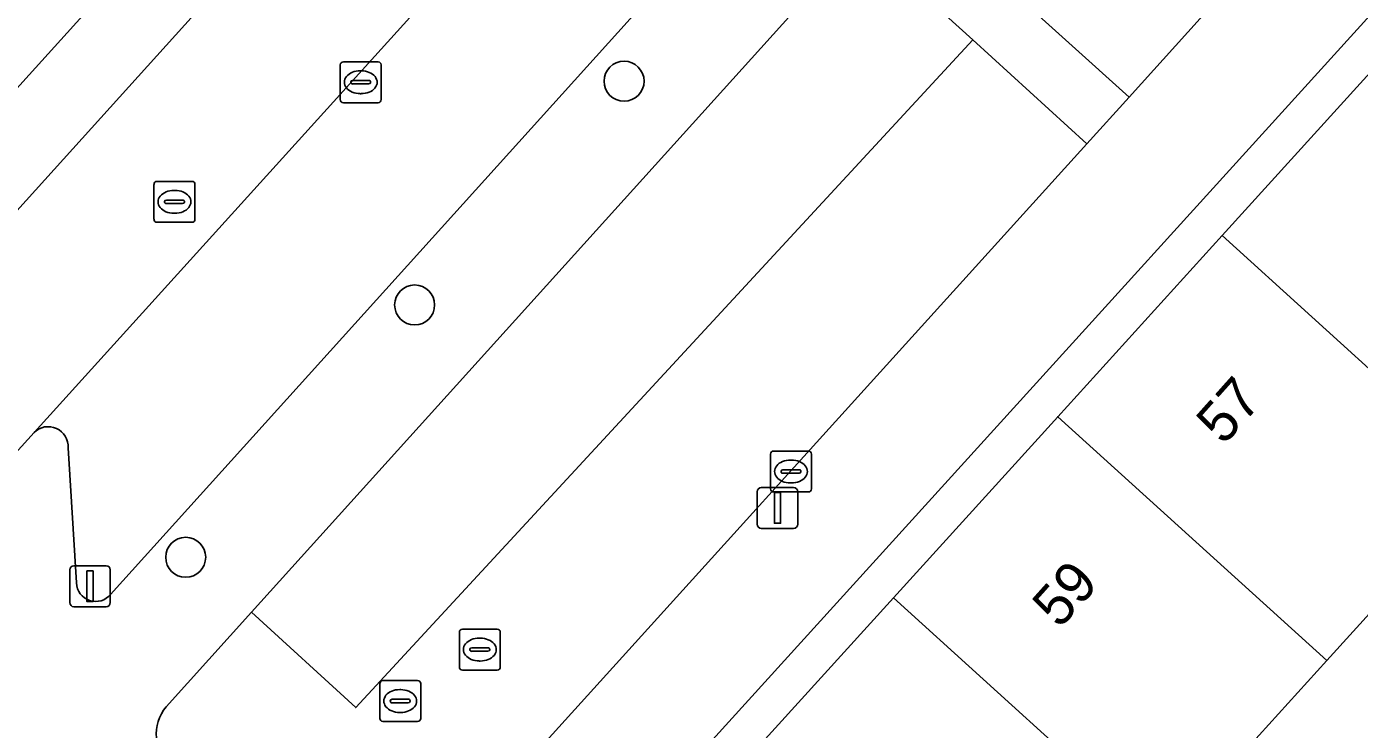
# Model space of a CAD drawing. Extents: x 159039 to 160102, y 381214 to 382524.
# Drawn here: x 159510.93 to 159543.52, y 381770.5 to 381787.69 of the extents above; entities that cross this region are included whole.
import ezdxf

# ---------------------------------------------------------------- set-up
doc = ezdxf.new("R2010")
doc.units = 0
for name, color, linetype in [('IMGEO_Boom', 7, 'Continuous'), ('IMGEO_Erf', 7, 'Continuous'), ('IMGEO_Groenvoorziening', 7, 'Continuous'), ('IMGEO_Kolk', 7, 'Continuous'), ('IMGEO_Lichtmast', 7, 'Continuous'), ('IMGEO_Pand', 7, 'Continuous'), ('IMGEO_Pand_nummerreeks', 7, 'Continuous'), ('IMGEO_Parkeervlak_open', 7, 'Continuous'), ('IMGEO_Rijbaan_lokaal_open', 7, 'Continuous'), ('IMGEO_Rioolput', 7, 'Continuous'), ('IMGEO_Voetpad_open', 7, 'Continuous')]:
    doc.layers.add(name, color=color, linetype=linetype)

msp = doc.modelspace()

# ---------------------------------------------------------------- linework, layer by layer
at = {"layer": 'IMGEO_Boom'}
for centre in [(159525.537, 381786.356), (159520.415, 381780.883), (159514.815, 381774.711)]:
    msp.add_circle(centre, 0.489, dxfattribs=at)
at = {"layer": 'IMGEO_Erf'}
for points in [[(159556.91, 381802.444), (159519.855, 381761.602)], [(159528.109, 381769.292), (159532.127, 381773.721), (159536.145, 381778.149), (159540.164, 381782.579), (159544.182, 381787.008)], [(159546.74, 381776.612), (159542.721, 381772.183), (159538.703, 381767.754), (159534.685, 381763.325), (159530.667, 381758.897), (159526.533, 381754.341), (159527.681, 381753.271), (159531.761, 381750.028), (159535.569, 381754.45), (159537.378, 381756.551)]]:
    msp.add_lwpolyline(points, dxfattribs=at)
at = {"layer": 'IMGEO_Groenvoorziening'}
for points in [[(159534.941, 381788.628), (159537.894, 381785.968), (159552.314, 381801.953)], [(159534.063, 381787.364), (159518.976, 381771.034), (159516.427, 381773.369)], [(159521.06, 381767.378), (159536.857, 381784.828), (159534.063, 381787.364)], [(159516.427, 381773.369), (159514.337, 381771.053)]]:
    msp.add_lwpolyline(points, dxfattribs=at)
msp.add_lwpolyline([(159516.427, 381773.369), (159518.976, 381771.034), (159534.063, 381787.364), (159531.315, 381789.859)], close=True, dxfattribs=at)
msp.add_arc((159515.166, 381770.375), 1.071, 140.7315, 227.7441, dxfattribs=at)
at = {"layer": 'IMGEO_Kolk'}
for p, q in [((159518.596, 381785.905), (159518.596, 381786.757)), ((159518.671, 381786.831), (159519.523, 381786.831)), ((159519.597, 381786.757), (159519.597, 381785.905)), ((159518.898, 381786.374), (159519.296, 381786.374)), ((159519.084, 381786.611), (159519.109, 381786.611)), ((159518.855, 381786.325), (159518.855, 381786.337)), ((159519.293, 381786.288), (159518.895, 381786.288)), ((159519.107, 381786.051), (159519.082, 381786.051)), ((159519.339, 381786.337), (159519.339, 381786.325)), ((159519.523, 381785.831), (159518.671, 381785.831)), ((159529.119, 381776.384), (159529.119, 381777.236)), ((159529.194, 381777.31), (159530.046, 381777.31)), ((159530.12, 381777.236), (159530.12, 381776.384)), ((159529.607, 381777.09), (159529.632, 381777.09)), ((159529.378, 381776.804), (159529.378, 381776.816)), ((159529.816, 381776.767), (159529.418, 381776.767)), ((159529.421, 381776.853), (159529.819, 381776.853)), ((159529.862, 381776.816), (159529.862, 381776.804)), ((159530.046, 381776.31), (159529.194, 381776.31)), ((159529.63, 381776.53), (159529.605, 381776.53))]:
    msp.add_line(p, q, dxfattribs=at)
for points in [[(159518.596, 381785.905), (159518.596, 381786.757)], [(159518.671, 381786.831), (159519.523, 381786.831)], [(159519.597, 381786.757), (159519.597, 381785.905)], [(159519.523, 381785.831), (159518.671, 381785.831)], [(159529.119, 381776.384), (159529.119, 381777.236)], [(159529.194, 381777.31), (159530.046, 381777.31)], [(159530.12, 381777.236), (159530.12, 381776.384)], [(159530.046, 381776.31), (159529.194, 381776.31)]]:
    msp.add_lwpolyline(points, dxfattribs=at)
for centre, radius, start, end in [((159518.673, 381786.755), 0.0765, 91.552, 178.448), ((159518.673, 381786.755), 0.0765, 91.552, 178.448), ((159519.521, 381786.755), 0.0765, 1.552, 88.448), ((159519.521, 381786.755), 0.0765, 1.552, 88.448), ((159518.895, 381786.334), 0.0403, 85.8775, 175.7526), ((159519.3, 381786.336), 0.0386, 1.7309, 96.639), ((159518.892, 381786.324), 0.0366, 178.938, 274.7102), ((159519.296, 381786.331), 0.043, 264.8664, 352.4533), ((159518.673, 381785.907), 0.0765, 181.552, 268.448), ((159518.673, 381785.907), 0.0765, 181.552, 268.448), ((159519.521, 381785.907), 0.0765, 271.552, 358.448), ((159519.521, 381785.907), 0.0765, 271.552, 358.448), ((159529.196, 381777.234), 0.0765, 91.552, 178.448), ((159529.196, 381777.234), 0.0765, 91.552, 178.448), ((159530.044, 381777.234), 0.0765, 1.552, 88.448), ((159530.044, 381777.234), 0.0765, 1.552, 88.448), ((159529.418, 381776.813), 0.0403, 85.8775, 175.7526), ((159529.415, 381776.803), 0.0366, 178.938, 274.7102), ((159529.819, 381776.81), 0.043, 264.8664, 352.4533), ((159529.823, 381776.815), 0.0386, 1.7309, 96.639), ((159529.196, 381776.386), 0.0765, 181.552, 268.448), ((159529.196, 381776.386), 0.0765, 181.552, 268.448), ((159530.044, 381776.386), 0.0765, 271.552, 358.448), ((159530.044, 381776.386), 0.0765, 271.552, 358.448)]:
    msp.add_arc(centre, radius, start, end, dxfattribs=at)
for centre, major_axis, ratio, start_param, end_param in [((159519.083, 381786.331), (-0.387, 0.002), 0.722429, 4.712389, 7.853982), ((159519.108, 381786.331), (-0.39, 0.002), 0.717154, 1.570796, 4.712389), ((159529.606, 381776.81), (-0.387, 0.002), 0.722429, 4.712389, 7.853982), ((159529.631, 381776.81), (-0.39, 0.002), 0.717154, 1.570796, 4.712389)]:
    msp.add_ellipse(centre, major_axis=major_axis, ratio=ratio, start_param=start_param, end_param=end_param, dxfattribs=at)
at = {"layer": 'IMGEO_Lichtmast'}
for p, q in [((159528.793, 381775.518), (159528.793, 381776.318)), ((159528.793, 381776.318), (159528.793, 381775.518)), ((159528.893, 381776.418), (159529.683, 381776.418)), ((159529.683, 381776.418), (159528.893, 381776.418)), ((159529.783, 381776.318), (159529.783, 381775.518)), ((159529.783, 381775.518), (159529.783, 381776.318)), ((159529.683, 381775.418), (159528.893, 381775.418)), ((159528.893, 381775.418), (159529.683, 381775.418)), ((159511.981, 381773.603), (159511.981, 381774.403)), ((159511.981, 381774.403), (159511.981, 381773.603)), ((159512.081, 381774.503), (159512.871, 381774.503)), ((159512.871, 381774.503), (159512.081, 381774.503)), ((159512.971, 381774.403), (159512.971, 381773.603)), ((159512.971, 381773.603), (159512.971, 381774.403)), ((159512.871, 381773.503), (159512.081, 381773.503)), ((159512.081, 381773.503), (159512.871, 381773.503))]:
    msp.add_line(p, q, dxfattribs=at)
for points in [[(159529.213, 381776.293), (159529.363, 381776.293), (159529.363, 381775.543), (159529.213, 381775.543), (159529.213, 381776.293)], [(159512.401, 381774.378), (159512.551, 381774.378), (159512.551, 381773.628), (159512.401, 381773.628), (159512.401, 381774.378)]]:
    msp.add_lwpolyline(points, dxfattribs=at)
for centre, start, end in [((159528.893, 381776.318), 90, 180), ((159528.893, 381776.318), 90, 180), ((159529.683, 381776.318), 0, 90), ((159529.683, 381776.318), 360, 90), ((159528.893, 381775.518), 180, 270), ((159528.893, 381775.518), 180, 270), ((159529.683, 381775.518), 270, 0), ((159529.683, 381775.518), 270, 0), ((159512.081, 381774.403), 90, 180), ((159512.081, 381774.403), 90, 180), ((159512.871, 381774.403), 0, 90), ((159512.871, 381774.403), 360, 90), ((159512.081, 381773.603), 180, 270), ((159512.081, 381773.603), 180, 270), ((159512.871, 381773.603), 270, 0), ((159512.871, 381773.603), 270, 0)]:
    msp.add_arc(centre, 0.1, start, end, dxfattribs=at)
at = {"layer": 'IMGEO_Pand'}
for points in [[(159546.74, 381776.612), (159550.758, 381781.041), (159544.182, 381787.008), (159540.164, 381782.579)], [(159542.721, 381772.183), (159546.74, 381776.612), (159540.164, 381782.579), (159536.145, 381778.149)], [(159532.127, 381773.721), (159538.703, 381767.754), (159542.721, 381772.183), (159536.145, 381778.149)], [(159528.109, 381769.292), (159534.685, 381763.325), (159538.703, 381767.754), (159532.127, 381773.721)]]:
    msp.add_lwpolyline(points, close=True, dxfattribs=at)
at = {"layer": 'IMGEO_Parkeervlak_open'}
for points in [[(159542.646, 381812.762), (159537.05, 381806.473), (159533.847, 381802.894), (159511.108, 381777.766)], [(159512.977, 381773.804), (159541.877, 381805.831)], [(159511.941, 381777.39), (159512.143, 381774.083)]]:
    msp.add_lwpolyline(points, dxfattribs=at)
msp.add_lwpolyline([(159520.178, 381796.676), (159508.977, 381784.292), (159510.46, 381782.935), (159521.64, 381795.325)], close=True, dxfattribs=at)
for centre, radius, start, end in [((159511.451, 381777.416), 0.49, 356.951, 134.4621), ((159512.613, 381774.101), 0.47, 182.1773, 320.8292)]:
    msp.add_arc(centre, radius, start, end, dxfattribs=at)
at = {"layer": 'IMGEO_Rijbaan_lokaal_open'}
msp.add_lwpolyline([(159492.635, 381757.366), (159505.968, 381772.09), (159511.108, 381777.766), (159533.847, 381802.894), (159530.884, 381805.57), (159529.238, 381803.745), (159527.763, 381805.071), (159527.126, 381804.363), (159521.088, 381797.682), (159520.178, 381796.676), (159521.64, 381795.325), (159510.46, 381782.935), (159508.977, 381784.292), (159507.773, 381782.961), (159503.057, 381777.726), (159502.12, 381776.684), (159503.595, 381775.326), (159491.718, 381762.164)], dxfattribs=at)
at = {"layer": 'IMGEO_Rioolput'}
for p, q in [((159514.04, 381782.979), (159514.04, 381783.831)), ((159514.115, 381783.905), (159514.967, 381783.905)), ((159515.041, 381783.831), (159515.041, 381782.979)), ((159514.342, 381783.448), (159514.74, 381783.448)), ((159514.528, 381783.685), (159514.553, 381783.685)), ((159514.299, 381783.399), (159514.299, 381783.411)), ((159514.737, 381783.362), (159514.339, 381783.362)), ((159514.551, 381783.125), (159514.526, 381783.125)), ((159514.783, 381783.411), (159514.783, 381783.399)), ((159514.967, 381782.905), (159514.115, 381782.905)), ((159521.508, 381772.028), (159521.508, 381772.88)), ((159521.583, 381772.954), (159522.435, 381772.954)), ((159521.996, 381772.734), (159522.021, 381772.734)), ((159522.509, 381772.88), (159522.509, 381772.028)), ((159521.767, 381772.448), (159521.767, 381772.46)), ((159522.205, 381772.411), (159521.807, 381772.411)), ((159521.81, 381772.497), (159522.208, 381772.497)), ((159522.251, 381772.46), (159522.251, 381772.448)), ((159522.019, 381772.174), (159521.994, 381772.174)), ((159519.636, 381771.695), (159520.488, 381771.695)), ((159522.435, 381771.954), (159521.583, 381771.954)), ((159519.561, 381770.769), (159519.561, 381771.621)), ((159520.049, 381771.475), (159520.074, 381771.475)), ((159520.562, 381771.621), (159520.562, 381770.769)), ((159519.82, 381771.189), (159519.82, 381771.201)), ((159520.258, 381771.152), (159519.86, 381771.152)), ((159519.863, 381771.238), (159520.261, 381771.238)), ((159520.304, 381771.201), (159520.304, 381771.189)), ((159520.072, 381770.915), (159520.047, 381770.915)), ((159520.488, 381770.695), (159519.636, 381770.695))]:
    msp.add_line(p, q, dxfattribs=at)
for points in [[(159514.04, 381782.979), (159514.04, 381783.831)], [(159514.115, 381783.905), (159514.967, 381783.905)], [(159515.041, 381783.831), (159515.041, 381782.979)], [(159514.967, 381782.905), (159514.115, 381782.905)], [(159521.508, 381772.028), (159521.508, 381772.88)], [(159521.583, 381772.954), (159522.435, 381772.954)], [(159522.509, 381772.88), (159522.509, 381772.028)], [(159519.636, 381771.695), (159520.488, 381771.695)], [(159522.435, 381771.954), (159521.583, 381771.954)], [(159519.561, 381770.769), (159519.561, 381771.621)], [(159520.562, 381771.621), (159520.562, 381770.769)], [(159520.488, 381770.695), (159519.636, 381770.695)]]:
    msp.add_lwpolyline(points, dxfattribs=at)
for centre, radius, start, end in [((159514.117, 381783.829), 0.0765, 91.552, 178.448), ((159514.117, 381783.829), 0.0765, 91.552, 178.448), ((159514.965, 381783.829), 0.0765, 1.552, 88.448), ((159514.965, 381783.829), 0.0765, 1.552, 88.448), ((159514.339, 381783.408), 0.0403, 85.8775, 175.7526), ((159514.744, 381783.41), 0.0386, 1.7309, 96.639), ((159514.336, 381783.398), 0.0366, 178.938, 274.7102), ((159514.74, 381783.405), 0.043, 264.8664, 352.4533), ((159514.117, 381782.981), 0.0765, 181.552, 268.448), ((159514.117, 381782.981), 0.0765, 181.552, 268.448), ((159514.965, 381782.981), 0.0765, 271.552, 358.448), ((159514.965, 381782.981), 0.0765, 271.552, 358.448), ((159521.585, 381772.878), 0.0765, 91.552, 178.448), ((159521.585, 381772.878), 0.0765, 91.552, 178.448), ((159522.433, 381772.878), 0.0765, 1.552, 88.448), ((159522.433, 381772.878), 0.0765, 1.552, 88.448), ((159521.807, 381772.457), 0.0403, 85.8775, 175.7526), ((159521.804, 381772.447), 0.0366, 178.938, 274.7102), ((159522.208, 381772.454), 0.043, 264.8664, 352.4533), ((159522.212, 381772.459), 0.0386, 1.7309, 96.639), ((159521.585, 381772.03), 0.0765, 181.552, 268.448), ((159521.585, 381772.03), 0.0765, 181.552, 268.448), ((159522.433, 381772.03), 0.0765, 271.552, 358.448), ((159522.433, 381772.03), 0.0765, 271.552, 358.448), ((159519.638, 381771.619), 0.0765, 91.552, 178.448), ((159519.638, 381771.619), 0.0765, 91.552, 178.448), ((159520.486, 381771.619), 0.0765, 1.552, 88.448), ((159520.486, 381771.619), 0.0765, 1.552, 88.448), ((159519.86, 381771.198), 0.0403, 85.8775, 175.7526), ((159519.857, 381771.188), 0.0366, 178.938, 274.7102), ((159520.261, 381771.195), 0.043, 264.8664, 352.4533), ((159520.265, 381771.2), 0.0386, 1.7309, 96.639), ((159519.638, 381770.771), 0.0765, 181.552, 268.448), ((159519.638, 381770.771), 0.0765, 181.552, 268.448), ((159520.486, 381770.771), 0.0765, 271.552, 358.448), ((159520.486, 381770.771), 0.0765, 271.552, 358.448)]:
    msp.add_arc(centre, radius, start, end, dxfattribs=at)
for centre, major_axis, ratio, start_param, end_param in [((159514.527, 381783.405), (-0.387, 0.002), 0.722429, 4.712389, 7.853982), ((159514.552, 381783.405), (-0.39, 0.002), 0.717154, 1.570796, 4.712389), ((159521.995, 381772.454), (-0.387, 0.002), 0.722429, 4.712389, 7.853982), ((159522.02, 381772.454), (-0.39, 0.002), 0.717154, 1.570796, 4.712389), ((159520.048, 381771.195), (-0.387, 0.002), 0.722429, 4.712389, 7.853982), ((159520.073, 381771.195), (-0.39, 0.002), 0.717154, 1.570796, 4.712389)]:
    msp.add_ellipse(centre, major_axis=major_axis, ratio=ratio, start_param=start_param, end_param=end_param, dxfattribs=at)
at = {"layer": 'IMGEO_Voetpad_open'}
for points in [[(159484.621, 381757.257), (159486.874, 381759.764), (159489.416, 381762.559), (159490.252, 381763.489), (159502.12, 381776.684), (159503.057, 381777.726), (159507.773, 381782.961), (159508.977, 381784.292), (159520.178, 381796.676), (159521.088, 381797.682), (159527.126, 381804.363), (159527.763, 381805.071), (159535.61, 381813.79)], [(159514.337, 381771.053), (159516.427, 381773.369), (159531.315, 381789.859), (159534.063, 381787.364), (159536.857, 381784.828), (159537.894, 381785.968), (159534.941, 381788.628), (159531.326, 381791.884), (159545.108, 381807.153), (159547.059, 381809.314), (159549.884, 381812.624)], [(159541.877, 381805.831), (159512.977, 381773.804)], [(159517.222, 381767.108), (159514.996, 381764.721), (159519.551, 381760.734), (159519.855, 381761.602), (159556.91, 381802.444), (159558.749, 381804.5)], [(159552.314, 381801.953), (159537.894, 381785.968), (159536.857, 381784.828), (159521.06, 381767.378)], [(159511.108, 381777.766), (159505.968, 381772.09), (159507.563, 381770.646), (159508.032, 381770.22), (159514.64, 381764.31), (159514.996, 381764.721), (159517.222, 381767.108), (159514.446, 381769.582)], [(159512.143, 381774.083), (159511.941, 381777.39)]]:
    msp.add_lwpolyline(points, dxfattribs=at)
for centre, radius, start, end in [((159511.451, 381777.416), 0.49, 356.951, 134.4621), ((159512.613, 381774.101), 0.47, 182.1773, 320.8292), ((159515.166, 381770.375), 1.071, 140.7315, 227.7441)]:
    msp.add_arc(centre, radius, start, end, dxfattribs=at)

# ---------------------------------------------------------------- texts
at = {"layer": 'IMGEO_Pand_nummerreeks'}
for s, p in [('57', (159540.199, 381777.428)), ('59', (159536.188, 381772.941))]:
    msp.add_text(s, height=1, rotation=48.2101, dxfattribs=at).set_placement(p)

doc.saveas('drawing.dxf')
